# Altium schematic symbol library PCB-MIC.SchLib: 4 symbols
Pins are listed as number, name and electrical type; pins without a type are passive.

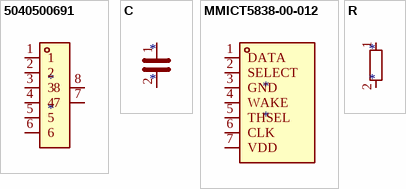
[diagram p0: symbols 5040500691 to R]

## 5040500691
designator *
pins: 1, 2, 3, 4, 5, 6, 7, 8

## C
designator *
pins: 1, 2

## MMICT5838-00-012
designator *
pins: 1 DATA, 2 SELECT, 3 GND, 4 WAKE, 5 THSEL, 6 CLK, 7 VDD

## R
designator *
pins: 1, 2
